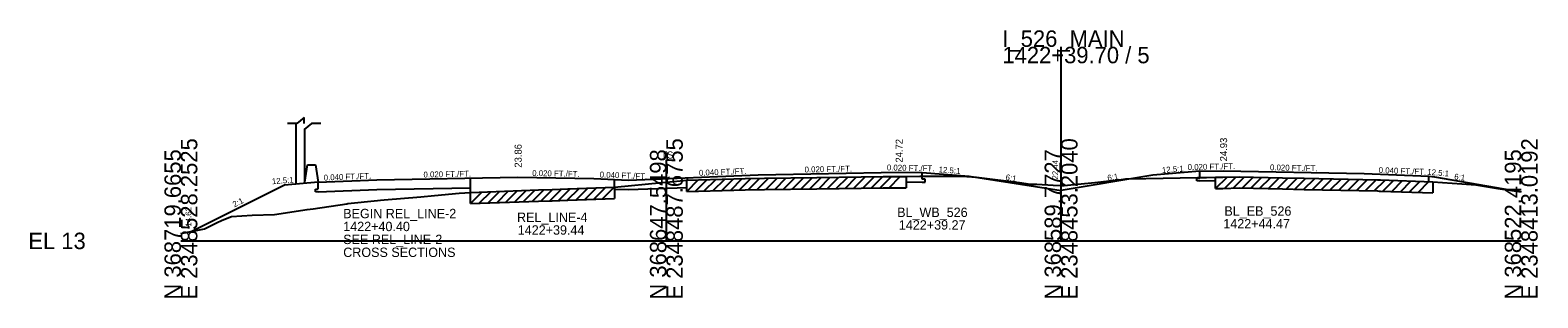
# Model space of a CAD drawing. Extents: x -170 to 2527928, y -10 to 1619750.
# Drawn here: x 3974.3 to 4231.3, y 2490.3 to 2535.9 of the extents above; entities that cross this region are included whole.
import ezdxf

# ---------------------------------------------------------------- set-up
doc = ezdxf.new("R2010")
doc.units = 0
for name, color, linetype in [('Default', 7, 'Continuous'), ('RD_GPK_XS_Cell', 7, 'Continuous'), ('RD_PD_NOISE-WALL-GM', 7, 'Continuous'), ('RD_XS_Base', 7, 'Continuous'), ('RD_XS_EarthShd', 7, 'Continuous'), ('RD_XS_ExGround', 7, 'Continuous'), ('RD_XS_ExPaveRet', 7, 'Continuous'), ('RD_XS_MatchLine', 7, 'Continuous'), ('RD_XS_Pave', 7, 'Continuous'), ('RD_XS_PaveShd', 7, 'Continuous'), ('RD_XS_TieSlope', 7, 'Continuous'), ('RD_XS_TX_Elev_EX', 7, 'Continuous'), ('RD_XS_TX_Slope', 7, 'Continuous'), ('RD_XS_TX_Station', 7, 'Continuous')]:
    doc.layers.add(name, color=color, linetype=linetype)

msp = doc.modelspace()

# ---------------------------------------------------------------- linework, layer by layer
at = {"layer": 'Default'}
for p, q in [((4019.74, 2520), (4018.16, 2520)), ((4020.99, 2521.02), (4019.74, 2520)), ((4020.99, 2520), (4020.99, 2521.02)), ((4022.24, 2520), (4020.99, 2518.97)), ((4023.84, 2520), (4022.24, 2520))]:
    msp.add_line(p, q, dxfattribs=at)
at = {"layer": 'RD_GPK_XS_Cell'}
for p, q in [((4150.03, 2500), (4150.03, 2533.05)), ((4000, 2500), (4082.75, 2500)), ((4082.75, 2500), (4150.03, 2500)), ((4150.03, 2500), (4228.46, 2500))]:
    msp.add_line(p, q, dxfattribs=at)
at = {"layer": 'RD_PD_NOISE-WALL-GM'}
for p, q in [((4019.62, 2520), (4019.62, 2509.68)), ((4021.12, 2509.8), (4021.12, 2519.07)), ((4021.12, 2509.98), (4021.6, 2512.98)), ((4021.6, 2512.98), (4022.94, 2512.98)), ((4022.94, 2512.98), (4023.42, 2509.98))]:
    msp.add_line(p, q, dxfattribs=at)
at = {"layer": 'RD_XS_Base'}
for p, q in [((4126.38, 2510.5), (4126.38, 2511.64)), ((4173.68, 2510.72), (4173.68, 2511.85)), ((4212.72, 2510.1), (4212.72, 2511.02)), ((4022.92, 2508.83), (4023.42, 2508.85)), ((4022.92, 2508.33), (4022.92, 2508.83)), ((4023.42, 2508.35), (4022.92, 2508.33)), ((4023.42, 2508.85), (4023.42, 2509.98)), ((4023.42, 2508.35), (4033.42, 2508.75)), ((4033.42, 2508.75), (4049.37, 2509.06)), ((4049.37, 2508.27), (4049.37, 2510.7)), ((4073.91, 2508.83), (4073.91, 2510.46)), ((4073.91, 2508.83), (4076.3, 2508.73)), ((4076.3, 2508.73), (4086.22, 2509.12)), ((4086.37, 2510.35), (4086.37, 2510.77)), ((4123.6, 2510.06), (4126.38, 2510)), ((4126.88, 2510.49), (4126.38, 2510.5)), ((4126.38, 2510), (4126.88, 2509.99)), ((4126.88, 2509.99), (4126.88, 2510.49)), ((4173.18, 2510.71), (4173.68, 2510.72)), ((4173.18, 2510.21), (4173.18, 2510.71)), ((4173.68, 2510.22), (4173.18, 2510.21)), ((4173.68, 2510.22), (4176.38, 2510.27))]:
    msp.add_line(p, q, dxfattribs=at)
at = {"layer": 'RD_XS_EarthShd'}
for p, q in [((4126.38, 2511.64), (4134.38, 2511)), ((4173.68, 2511.85), (4165.68, 2511.21)), ((4017.66, 2509.52), (4001.85, 2501.62)), ((4023.42, 2509.98), (4017.66, 2509.52))]:
    msp.add_line(p, q, dxfattribs=at)
at = {"layer": 'RD_XS_ExGround'}
msp.add_lwpolyline([(4000, 2501.25), (4004.01, 2502.04), (4006.09, 2503.06), (4007.02, 2503.53), (4008.61, 2504.15), (4012.14, 2504.37), (4015.97, 2504.5), (4021.55, 2505.34), (4022.57, 2505.49), (4028.26, 2506.34), (4028.45, 2506.36), (4028.48, 2506.37), (4033.54, 2506.89), (4034.01, 2506.94), (4034.65, 2507.01), (4040.88, 2507.51), (4043.21, 2507.71), (4047.44, 2508.12), (4049.37, 2508.27), (4060.94, 2508.69), (4063.31, 2508.77), (4065.98, 2508.87), (4073.91, 2509.15), (4082.05, 2509.97), (4082.75, 2510.03), (4086.22, 2510.35), (4094.24, 2510.57), (4096.19, 2510.62), (4099.5, 2510.67), (4108.42, 2510.8), (4112.22, 2510.86), (4119.69, 2510.96), (4121.13, 2510.95), (4123.6, 2510.95), (4125.94, 2511.01), (4133.15, 2511.02), (4135.62, 2510.84), (4142.97, 2509.93), (4144.79, 2509.69), (4145.9, 2509.64), (4148.66, 2509.5), (4150.24, 2509.43), (4150.57, 2509.46), (4155.76, 2509.96), (4160.25, 2510.48), (4161.07, 2510.59), (4164.47, 2510.6), (4173.28, 2510.82), (4174.81, 2510.82), (4176.38, 2510.83), (4177.62, 2510.86), (4180.36, 2510.93), (4187.76, 2510.76), (4191.49, 2510.67), (4203.95, 2510.41), (4204.24, 2510.41), (4204.5, 2510.4), (4213.37, 2510.08), (4218.34, 2509.7), (4220.7, 2509.54), (4224.5, 2508.95), (4228.46, 2508.37)], dxfattribs=at)
at = {"layer": 'RD_XS_ExPaveRet'}
for p, q in [((4105.72, 2508.85), (4107.66, 2510.79)), ((4107.22, 2508.87), (4109.16, 2510.81)), ((4108.72, 2508.89), (4110.66, 2510.83)), ((4110.22, 2508.91), (4112.16, 2510.86)), ((4111.72, 2508.93), (4113.66, 2510.88)), ((4113.22, 2508.95), (4115.16, 2510.9)), ((4114.72, 2508.97), (4116.66, 2510.92)), ((4116.22, 2508.99), (4118.16, 2510.94)), ((4117.72, 2509.01), (4119.66, 2510.96)), ((4119.22, 2509.04), (4121.13, 2510.95)), ((4120.72, 2509.04), (4122.63, 2510.95)), ((4123.6, 2510.95), (4123.6, 2509.03)), ((4176.38, 2508.92), (4178.35, 2510.88)), ((4176.38, 2508.92), (4176.38, 2510.83)), ((4177.88, 2508.95), (4179.85, 2510.91)), ((4179.38, 2508.99), (4181.3, 2510.91)), ((4180.88, 2509), (4182.76, 2510.87)), ((4182.38, 2508.96), (4184.26, 2510.84)), ((4183.88, 2508.93), (4185.76, 2510.8)), ((4049.37, 2506.35), (4051.36, 2508.34)), ((4049.37, 2506.35), (4049.37, 2508.27)), ((4050.87, 2506.4), (4052.86, 2508.39)), ((4052.37, 2506.46), (4054.36, 2508.45)), ((4053.87, 2506.51), (4055.86, 2508.5)), ((4055.37, 2506.57), (4057.36, 2508.56)), ((4056.87, 2506.62), (4058.86, 2508.61)), ((4058.37, 2506.68), (4060.36, 2508.67)), ((4059.87, 2506.73), (4061.86, 2508.72)), ((4061.37, 2506.78), (4063.36, 2508.77)), ((4062.87, 2506.83), (4064.87, 2508.83)), ((4064.37, 2506.89), (4066.37, 2508.89)), ((4065.87, 2506.95), (4067.86, 2508.94)), ((4067.37, 2507), (4069.36, 2508.99)), ((4068.87, 2507.06), (4070.86, 2509.04)), ((4070.37, 2507.11), (4072.36, 2509.1)), ((4071.87, 2507.16), (4073.86, 2509.15)), ((4073.91, 2509.15), (4073.91, 2507.23)), ((4086.22, 2508.43), (4088.19, 2510.4)), ((4086.22, 2508.43), (4086.22, 2510.35)), ((4086.22, 2508.43), (4094.24, 2508.65)), ((4087.72, 2508.47), (4089.69, 2510.44)), ((4089.22, 2508.51), (4091.19, 2510.48)), ((4090.72, 2508.56), (4092.69, 2510.53)), ((4092.22, 2508.6), (4094.19, 2510.57)), ((4093.72, 2508.64), (4095.69, 2510.61)), ((4094.24, 2508.65), (4096.19, 2508.7)), ((4095.22, 2508.68), (4097.17, 2510.64)), ((4096.19, 2508.7), (4099.5, 2508.75)), ((4096.72, 2508.71), (4098.66, 2510.66)), ((4098.22, 2508.73), (4100.16, 2510.68)), ((4099.5, 2508.75), (4108.42, 2508.89)), ((4099.72, 2508.76), (4101.66, 2510.7)), ((4101.22, 2508.78), (4103.16, 2510.72)), ((4102.72, 2508.8), (4104.66, 2510.75)), ((4104.22, 2508.82), (4106.16, 2510.77)), ((4108.42, 2508.89), (4112.22, 2508.94)), ((4112.22, 2508.94), (4119.69, 2509.04)), ((4119.69, 2509.04), (4121.13, 2509.03)), ((4121.13, 2509.03), (4123.6, 2509.03)), ((4176.38, 2508.92), (4177.62, 2508.94)), ((4177.62, 2508.94), (4180.36, 2509.01)), ((4180.36, 2509.01), (4187.76, 2508.84)), ((4185.38, 2508.9), (4187.26, 2510.77)), ((4186.88, 2508.86), (4188.76, 2510.74)), ((4187.76, 2508.84), (4191.49, 2508.76)), ((4188.38, 2508.83), (4190.26, 2510.7)), ((4189.88, 2508.79), (4191.76, 2510.67)), ((4191.38, 2508.76), (4193.26, 2510.64)), ((4191.49, 2508.76), (4203.95, 2508.5)), ((4192.88, 2508.73), (4194.76, 2510.61)), ((4194.38, 2508.7), (4196.26, 2510.57)), ((4195.88, 2508.67), (4197.76, 2510.54)), ((4197.38, 2508.63), (4199.26, 2510.51)), ((4198.88, 2508.6), (4200.76, 2510.48)), ((4200.38, 2508.57), (4202.26, 2510.45)), ((4201.88, 2508.54), (4203.76, 2510.42)), ((4203.38, 2508.51), (4205.25, 2510.37)), ((4203.95, 2508.5), (4204.24, 2508.49)), ((4204.24, 2508.49), (4204.5, 2508.48)), ((4204.5, 2508.48), (4213.37, 2508.16)), ((4204.88, 2508.47), (4206.73, 2510.32)), ((4206.38, 2508.41), (4208.23, 2510.26)), ((4207.88, 2508.36), (4209.73, 2510.21)), ((4209.38, 2508.3), (4211.23, 2510.15)), ((4210.88, 2508.25), (4212.73, 2510.1)), ((4213.37, 2510.08), (4213.37, 2508.16)), ((4049.37, 2506.35), (4060.94, 2506.77)), ((4060.94, 2506.77), (4063.31, 2506.85)), ((4063.31, 2506.85), (4065.98, 2506.96)), ((4065.98, 2506.96), (4073.91, 2507.23))]:
    msp.add_line(p, q, dxfattribs=at)
at = {"layer": 'RD_XS_MatchLine'}
msp.add_line((4082.75, 2500), (4082.75, 2513.78), dxfattribs=at)
at = {"layer": 'RD_XS_Pave'}
for p, q in [((4033.42, 2510.38), (4057.42, 2510.86)), ((4057.42, 2510.86), (4070.41, 2510.6)), ((4098.38, 2511.24), (4122.38, 2511.72)), ((4177.68, 2511.93), (4201.68, 2511.46))]:
    msp.add_line(p, q, dxfattribs=at)
at = {"layer": 'RD_XS_PaveShd'}
for p, q in [((4076.3, 2510.37), (4098.38, 2511.24)), ((4122.38, 2511.72), (4126.38, 2511.64)), ((4173.68, 2511.85), (4177.68, 2511.93)), ((4201.68, 2511.46), (4212.72, 2511.02)), ((4023.42, 2509.98), (4033.42, 2510.38)), ((4070.41, 2510.6), (4076.3, 2510.37))]:
    msp.add_line(p, q, dxfattribs=at)
at = {"layer": 'RD_XS_TieSlope'}
for p, q in [((4134.38, 2511), (4150.03, 2508.61)), ((4165.68, 2511.21), (4150.03, 2508.61)), ((4212.72, 2511.02), (4213.68, 2510.94)), ((4213.68, 2510.94), (4228.46, 2508.37))]:
    msp.add_line(p, q, dxfattribs=at)

# ---------------------------------------------------------------- texts
at = {"layer": 'RD_GPK_XS_Cell'}
for s, p in [('I_526_MAIN', (4140.03, 2533.05)), ('1422+39.70 / 5', (4140.03, 2530.25)), ('EL 13', (3974, 2498.6))]:
    msp.add_text(s, height=2.8, dxfattribs=at).set_placement(p)
for s, p in [('E 2348528.2525', (4002.8, 2490)), ('E 2348487.6755', (4085.55, 2490)), ('E 2348453.2040', (4152.83, 2490)), ('E 2348413.0192', (4231.26, 2490)), ('N 368719.6655', (4000, 2490)), ('N 368647.5498', (4082.75, 2490)), ('N 368589.7727', (4150.03, 2490)), ('N 368522.4195', (4228.46, 2490))]:
    msp.add_text(s, height=2.8, rotation=90, dxfattribs=at).set_placement(p)
at = {"layer": 'RD_XS_MatchLine'}
msp.add_text('TS', height=1.2, dxfattribs=at).set_placement((4081.89, 2514.03))
at = {"layer": 'RD_XS_TX_Elev_EX'}
msp.add_text('22.44', height=1, rotation=90, dxfattribs=at).set_placement((4149.53, 2510.44))
at = {"layer": 'RD_XS_TX_Slope'}
for s, rotation, p in [('12.5:1', 4.5739, (4015.55, 2509.64)), ('0.040 FT./FT.', 2.2906, (4024.36, 2510.27)), ('0.020 FT./FT.', 1.1458, (4041.36, 2510.79)), ('0.020 FT./FT.', 358.8542, (4059.87, 2511.06)), ('0.040 FT./FT.', 357.7094, (4071.37, 2510.81)), ('0.040 FT./FT.', 2.2762, (4088.32, 2511.09)), ('0.020 FT./FT.', 1.1314, (4106.32, 2511.65)), ('0.020 FT./FT.', 358.8402, (4120.33, 2512.01)), ('12.5:1', 355.4261, (4129.13, 2511.68)), ('6:1', 350.5377, (4140.51, 2510.38)), ('6:1', 9.4623, (4158.01, 2510.22)), ('12.5:1', 4.5739, (4167.26, 2511.55)), ('0.020 FT./FT.', 1.1592, (4171.62, 2512.06)), ('0.020 FT./FT.', 358.8679, (4185.63, 2512.03)), ('0.040 FT./FT.', 357.7094, (4204.15, 2511.58)), ('12.5:1', 355.4261, (4212.42, 2511.26)), ('6:1', 352.6182, (4217, 2510.48)), ('14.62', 90, (4001.79, 2502.43)), ('2:1', 26.5651, (4009.13, 2505.69))]:
    msp.add_text(s, height=1, rotation=rotation, dxfattribs=at).set_placement(p)
at = {"layer": 'RD_XS_TX_Station'}
for s, p in [(' 23.86', (4058.08, 2512.03)), (' 24.72', (4123.03, 2512.89)), (' 24.93', (4178.33, 2513.11))]:
    msp.add_text(s, height=1.2, rotation=90, dxfattribs=at).set_placement(p)
for s, p in [('BL_WB_526', (4122.09, 2504.07)), ('BL_EB_526', (4177.87, 2504.29)), ('1422+40.40', (4027.67, 2501.66)), ('BEGIN REL_LINE-2', (4027.67, 2503.86)), ('REL_LINE-4', (4057.29, 2503.23)), ('1422+39.27', (4122.38, 2501.92)), ('1422+44.47', (4177.68, 2502.13)), ('SEE REL_LINE-2', (4027.67, 2499.46)), ('1422+39.44', (4057.42, 2501.06)), ('CROSS SECTIONS', (4027.67, 2497.26))]:
    msp.add_text(s, height=1.6, dxfattribs=at).set_placement(p)

doc.saveas('drawing.dxf')
